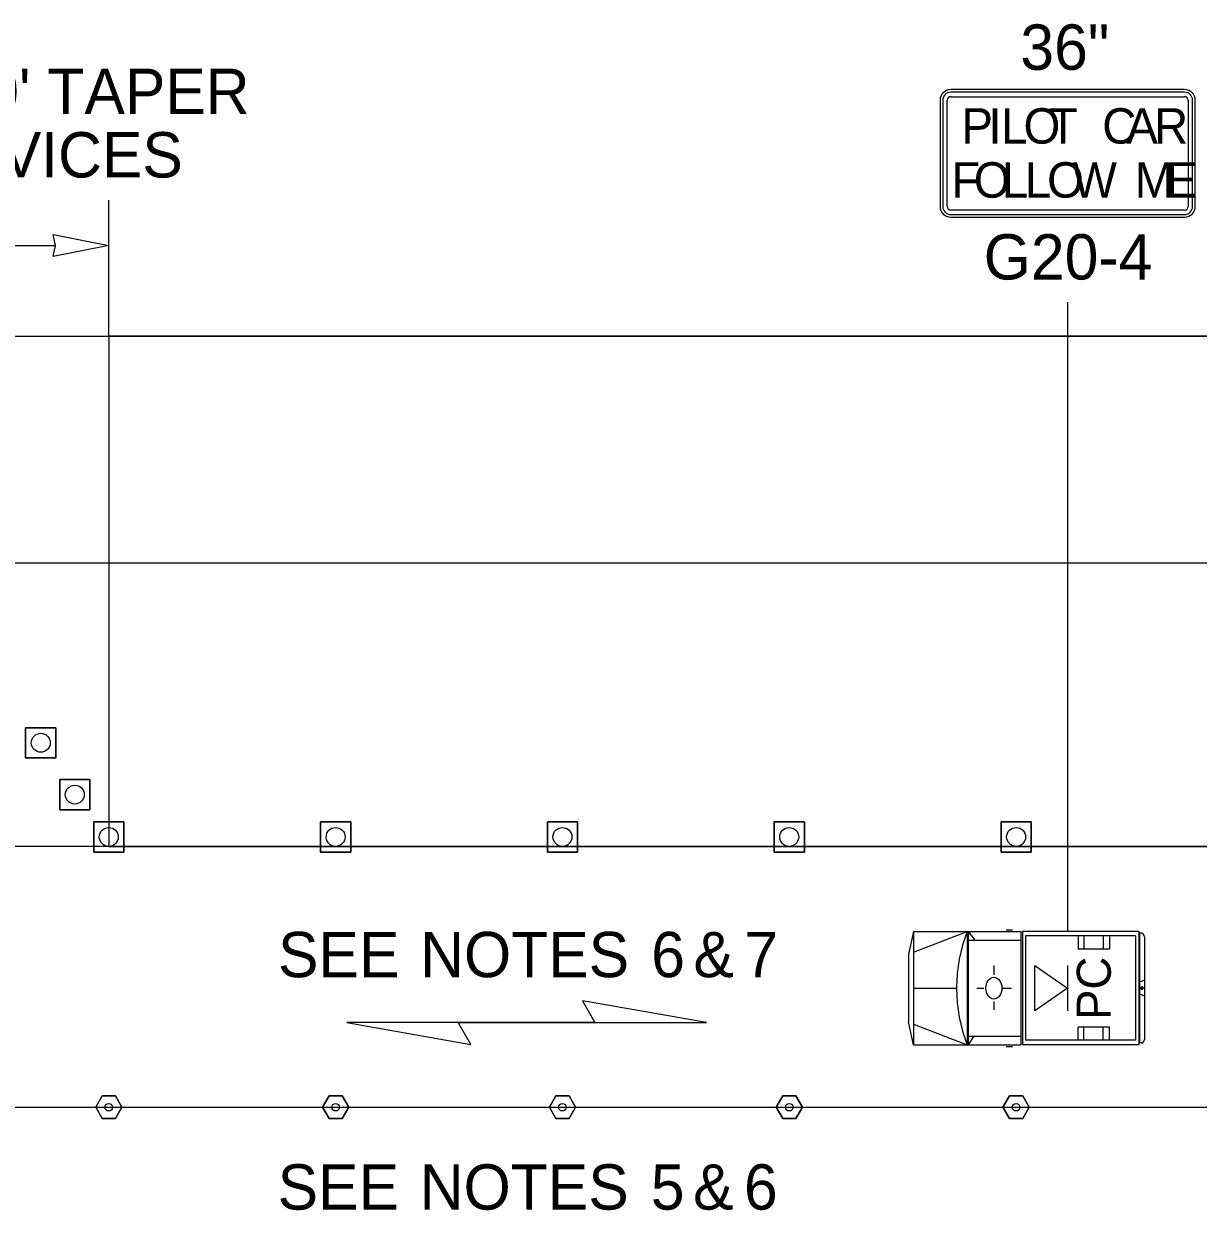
# Model space of a CAD drawing. Extents: x 99999.1 to 100095.7, y 99995 to 100010.7.
# Drawn here: x 100045 to 100047.071, y 100005.95 to 100008.044 of the extents above; entities that cross this region are included whole.
import ezdxf

# ---------------------------------------------------------------- set-up
doc = ezdxf.new("R2010")
doc.units = 0
for name, color, linetype in [('RD_ED_ShoulderPavedEdge', 7, 'Continuous'), ('RD_MK_LineEdgeWhite', 7, 'Continuous'), ('RD_MK_LineSkipCenter', 7, 'Continuous'), ('TR_SN_ConstructionSigns', 7, 'Continuous'), ('TR_WZ_MotoristVehicle', 7, 'Continuous'), ('TR_WZ_PortableSignMountBlk-Wht', 7, 'Continuous'), ('TR_WZ_TrafficCone', 7, 'Continuous'), ('TR_WZ_TubularMarker', 7, 'Continuous'), ('TR_WZ_WorkZoneDetails', 7, 'Continuous'), ('TR_WZ_WorkZoneTextCurrent', 7, 'Continuous')]:
    doc.layers.add(name, color=color, linetype=linetype)

msp = doc.modelspace()

# ---------------------------------------------------------------- linework, layer by layer
at = {"layer": 'RD_ED_ShoulderPavedEdge'}
msp.add_line((100040.1076, 100007.4923), (100055.6424, 100007.4923), dxfattribs=at)
at = {"layer": 'RD_MK_LineEdgeWhite'}
for p, q in [((100040.1076, 100007.0923), (100055.6424, 100007.0923)), ((100040.1076, 100006.1323), (100055.6424, 100006.1323))]:
    msp.add_line(p, q, dxfattribs=at)
at = {"layer": 'RD_MK_LineSkipCenter'}
msp.add_lwpolyline([(100051.15, 100006.5923), (100043.4767, 100006.5923)], dxfattribs=at)
at = {"layer": 'TR_SN_ConstructionSigns'}
for p, q in [((100047.0472, 100007.9273), (100046.6347, 100007.9273)), ((100047.0472, 100007.9226), (100046.6347, 100007.9226)), ((100046.6347, 100007.9148), (100047.0472, 100007.9148)), ((100047.0472, 100007.9226), (100047.0472, 100007.9226)), ((100046.6159, 100007.9086), (100046.6159, 100007.7211)), ((100046.6206, 100007.9086), (100046.6206, 100007.9086)), ((100046.6206, 100007.9086), (100046.6206, 100007.7211)), ((100046.6284, 100007.7211), (100046.6284, 100007.9086)), ((100047.0534, 100007.9086), (100047.0534, 100007.7211)), ((100047.0612, 100007.7211), (100047.0612, 100007.9086)), ((100047.0659, 100007.7211), (100047.0659, 100007.9086)), ((100047.0472, 100007.7148), (100046.6347, 100007.7148)), ((100046.6347, 100007.707), (100046.6347, 100007.707)), ((100046.6347, 100007.707), (100047.0472, 100007.707)), ((100046.6347, 100007.7023), (100047.0472, 100007.7023)), ((100047.0612, 100007.7211), (100047.0612, 100007.7211))]:
    msp.add_line(p, q, dxfattribs=at)
for centre, radius, start, end in [((100046.6347, 100007.9086), 0.0187, 90, 180), ((100046.6347, 100007.9086), 0.0141, 90, 180), ((100046.6347, 100007.9086), 0.00625, 90, 180), ((100047.0472, 100007.9086), 0.0187, 0, 90), ((100047.0472, 100007.9086), 0.0141, 0, 90), ((100047.0472, 100007.9086), 0.00625, 0, 90), ((100046.6347, 100007.7211), 0.0187, 180, 270), ((100046.6347, 100007.7211), 0.0141, 180, 270), ((100046.6347, 100007.7211), 0.00625, 180, 270), ((100047.0472, 100007.7211), 0.0141, 270, 0), ((100047.0472, 100007.7211), 0.00625, 270, 0), ((100047.0472, 100007.7211), 0.0187, 270, 0)]:
    msp.add_arc(centre, radius, start, end, dxfattribs=at)
at = {"layer": 'TR_WZ_MotoristVehicle'}
for p, q in [((100046.5693, 100006.4423), (100046.56, 100006.402)), ((100046.5693, 100006.4423), (100046.5693, 100006.2423)), ((100046.5693, 100006.4423), (100046.7582, 100006.4423)), ((100046.5693, 100006.4057), (100046.6638, 100006.4423)), ((100046.6638, 100006.4423), (100046.6638, 100006.2423)), ((100046.6655, 100006.4423), (100046.6655, 100006.2423)), ((100046.6655, 100006.4423), (100046.6775, 100006.4268)), ((100046.6655, 100006.4268), (100046.7582, 100006.4268)), ((100046.7324, 100006.4451), (100046.7438, 100006.4451)), ((100046.7582, 100006.4423), (100046.7582, 100006.2423)), ((100046.9667, 100006.4423), (100046.761, 100006.4423)), ((100046.761, 100006.4423), (100046.761, 100006.2423)), ((100046.9608, 100006.4344), (100046.7668, 100006.4344)), ((100046.7668, 100006.4344), (100046.7668, 100006.2503)), ((100046.8595, 100006.4344), (100046.8595, 100006.4113)), ((100046.8695, 100006.4344), (100046.8695, 100006.4113)), ((100046.9035, 100006.4344), (100046.9035, 100006.4113)), ((100046.9145, 100006.4344), (100046.9145, 100006.4113)), ((100046.9608, 100006.4344), (100046.9608, 100006.2503)), ((100046.9667, 100006.4423), (100046.9667, 100006.2423)), ((100046.9718, 100006.439), (100046.9674, 100006.439)), ((100046.9674, 100006.439), (100046.9674, 100006.2456)), ((100046.9763, 100006.4329), (100046.9763, 100006.2517)), ((100046.9145, 100006.4113), (100046.8595, 100006.4113)), ((100046.56, 100006.402), (100046.56, 100006.2827)), ((100046.7108, 100006.382), (100046.7108, 100006.3658)), ((100046.5693, 100006.3423), (100046.6452, 100006.3423)), ((100046.6807, 100006.3425), (100046.6933, 100006.3424)), ((100046.7249, 100006.342), (100046.7249, 100006.342)), ((100046.7417, 100006.3416), (100046.7268, 100006.3419)), ((100046.9763, 100006.3564), (100046.9674, 100006.3527)), ((100046.9739, 100006.3423), (100046.9698, 100006.3423)), ((100046.9718, 100006.3451), (100046.9718, 100006.3395)), ((100046.9763, 100006.3282), (100046.9674, 100006.332)), ((100046.7115, 100006.3039), (100046.7112, 100006.3189)), ((100046.5693, 100006.2423), (100046.56, 100006.2827)), ((100046.5693, 100006.279), (100046.6638, 100006.2423)), ((100046.6655, 100006.2578), (100046.7582, 100006.2578)), ((100046.6754, 100006.2578), (100046.6655, 100006.2423)), ((100046.8595, 100006.2503), (100046.8595, 100006.2733)), ((100046.9145, 100006.2733), (100046.8595, 100006.2733)), ((100046.8695, 100006.2503), (100046.8695, 100006.2733)), ((100046.9035, 100006.2503), (100046.9035, 100006.2733)), ((100046.9145, 100006.2503), (100046.9145, 100006.2733)), ((100046.5693, 100006.2423), (100046.7582, 100006.2423)), ((100046.7324, 100006.2395), (100046.7438, 100006.2395)), ((100046.9667, 100006.2423), (100046.761, 100006.2423)), ((100046.9608, 100006.2503), (100046.7668, 100006.2503)), ((100046.9718, 100006.2456), (100046.9674, 100006.2456))]:
    msp.add_line(p, q, dxfattribs=at)
for centre, major_axis, start_param, end_param in [((100046.7987, 100006.3423), (0, -0.2099), 4.215667, 5.208926), ((100046.9718, 100006.4329), (0, 0.0061), 4.712389, 6.283185), ((100046.9718, 100006.2517), (0, -0.0061), 0, 1.570796)]:
    msp.add_ellipse(centre, major_axis=major_axis, ratio=0.73155, start_param=start_param, end_param=end_param, dxfattribs=at)
for centre, major_axis in [((100046.7108, 100006.3423), (0, 0.0193)), ((100046.9718, 100006.3423), (0, 0.00282))]:
    msp.add_ellipse(centre, major_axis=major_axis, ratio=0.73155, dxfattribs=at)
at = {"layer": 'TR_WZ_PortableSignMountBlk-Wht'}
msp.add_line((100046.8406, 100006.3822), (100046.8406, 100006.3022), dxfattribs=at)
msp.add_lwpolyline([(100046.8406, 100006.3423), (100046.7832, 100006.3022), (100046.7832, 100006.3822)], close=True, dxfattribs=at)
at = {"layer": 'TR_WZ_TrafficCone'}
for points in [[(100045.0034, 100006.8017), (100045.0567, 100006.8017), (100045.0567, 100006.7484), (100045.0034, 100006.7484), (100045.0034, 100006.8017)], [(100045.0034, 100006.7484), (100045.0567, 100006.7484), (100045.0567, 100006.8017), (100045.0034, 100006.8017), (100045.0034, 100006.7484)], [(100045.0634, 100006.7104), (100045.1167, 100006.7104), (100045.1167, 100006.6571), (100045.0634, 100006.6571), (100045.0634, 100006.7104)], [(100045.0634, 100006.6571), (100045.1167, 100006.6571), (100045.1167, 100006.7104), (100045.0634, 100006.7104), (100045.0634, 100006.6571)], [(100045.1234, 100006.6357), (100045.1767, 100006.6357), (100045.1767, 100006.5823), (100045.1234, 100006.5823), (100045.1234, 100006.6357)], [(100045.1234, 100006.5823), (100045.1767, 100006.5823), (100045.1767, 100006.6357), (100045.1234, 100006.6357), (100045.1234, 100006.5823)], [(100045.5234, 100006.6357), (100045.5767, 100006.6357), (100045.5767, 100006.5823), (100045.5234, 100006.5823), (100045.5234, 100006.6357)], [(100045.5234, 100006.5823), (100045.5767, 100006.5823), (100045.5767, 100006.6357), (100045.5234, 100006.6357), (100045.5234, 100006.5823)], [(100045.9234, 100006.6357), (100045.9767, 100006.6357), (100045.9767, 100006.5823), (100045.9234, 100006.5823), (100045.9234, 100006.6357)], [(100045.9234, 100006.5823), (100045.9767, 100006.5823), (100045.9767, 100006.6357), (100045.9234, 100006.6357), (100045.9234, 100006.5823)], [(100046.3234, 100006.6357), (100046.3767, 100006.6357), (100046.3767, 100006.5823), (100046.3234, 100006.5823), (100046.3234, 100006.6357)], [(100046.3234, 100006.5823), (100046.3767, 100006.5823), (100046.3767, 100006.6357), (100046.3234, 100006.6357), (100046.3234, 100006.5823)], [(100046.7234, 100006.6357), (100046.7767, 100006.6357), (100046.7767, 100006.5823), (100046.7234, 100006.5823), (100046.7234, 100006.6357)], [(100046.7234, 100006.5823), (100046.7767, 100006.5823), (100046.7767, 100006.6357), (100046.7234, 100006.6357), (100046.7234, 100006.5823)]]:
    msp.add_lwpolyline(points, dxfattribs=at)
for centre in [(100045.03, 100006.7751), (100045.09, 100006.6837), (100045.15, 100006.609), (100045.55, 100006.609), (100045.95, 100006.609), (100046.35, 100006.609), (100046.75, 100006.609)]:
    msp.add_circle(centre, 0.0167, dxfattribs=at)
at = {"layer": 'TR_WZ_TubularMarker'}
for points in [[(100045.1269, 100006.1323), (100045.1385, 100006.1523), (100045.1616, 100006.1523), (100045.1731, 100006.1323), (100045.1616, 100006.1123), (100045.1385, 100006.1123)], [(100045.5269, 100006.1323), (100045.5385, 100006.1523), (100045.5616, 100006.1523), (100045.5731, 100006.1323), (100045.5616, 100006.1123), (100045.5385, 100006.1123)], [(100045.9269, 100006.1323), (100045.9385, 100006.1523), (100045.9616, 100006.1523), (100045.9731, 100006.1323), (100045.9616, 100006.1123), (100045.9385, 100006.1123)], [(100046.3269, 100006.1323), (100046.3385, 100006.1523), (100046.3616, 100006.1523), (100046.3731, 100006.1323), (100046.3616, 100006.1123), (100046.3385, 100006.1123)], [(100046.7269, 100006.1323), (100046.7385, 100006.1523), (100046.7616, 100006.1523), (100046.7731, 100006.1323), (100046.7616, 100006.1123), (100046.7385, 100006.1123)]]:
    msp.add_lwpolyline(points, close=True, dxfattribs=at)
for points in [[(100045.1385, 100006.1123), (100045.1616, 100006.1123), (100045.1731, 100006.1323), (100045.1616, 100006.1523), (100045.1385, 100006.1523), (100045.1269, 100006.1323), (100045.1385, 100006.1123)], [(100045.5385, 100006.1123), (100045.5616, 100006.1123), (100045.5731, 100006.1323), (100045.5616, 100006.1523), (100045.5385, 100006.1523), (100045.5269, 100006.1323), (100045.5385, 100006.1123)], [(100045.9385, 100006.1123), (100045.9616, 100006.1123), (100045.9731, 100006.1323), (100045.9616, 100006.1523), (100045.9385, 100006.1523), (100045.9269, 100006.1323), (100045.9385, 100006.1123)], [(100046.3385, 100006.1123), (100046.3616, 100006.1123), (100046.3731, 100006.1323), (100046.3616, 100006.1523), (100046.3385, 100006.1523), (100046.3269, 100006.1323), (100046.3385, 100006.1123)], [(100046.7385, 100006.1123), (100046.7616, 100006.1123), (100046.7731, 100006.1323), (100046.7616, 100006.1523), (100046.7385, 100006.1523), (100046.7269, 100006.1323), (100046.7385, 100006.1123)]]:
    msp.add_lwpolyline(points, dxfattribs=at)
for centre in [(100045.15, 100006.1323), (100045.55, 100006.1323), (100045.95, 100006.1323), (100046.35, 100006.1323), (100046.75, 100006.1323)]:
    msp.add_circle(centre, 0.00667, dxfattribs=at)
at = {"layer": 'TR_WZ_WorkZoneDetails'}
for p, q in [((100045.15, 100007.4923), (100045.15, 100007.7323)), ((100044.9204, 100007.6523), (100045.0563, 100007.6523)), ((100046.8406, 100007.5523), (100046.8406, 100006.4423)), ((100045.7663, 100006.2816), (100046.0074, 100006.2816)), ((100046.0074, 100006.2816), (100045.7663, 100006.2816))]:
    msp.add_line(p, q, dxfattribs=at)
for points in [[(100045.15, 100007.6523), (100045.0517, 100007.6331), (100045.0563, 100007.6523), (100045.0517, 100007.6716)], [(100045.15, 100007.4923), (100045.15, 100006.5923), (100049.9338, 100006.5923), (100049.9338, 100007.4923)], [(100046.2039, 100006.2816), (100045.9851, 100006.3202), (100046.0074, 100006.2816)], [(100045.5698, 100006.2816), (100045.7886, 100006.243), (100045.7663, 100006.2816)]]:
    msp.add_lwpolyline(points, close=True, dxfattribs=at)

# ---------------------------------------------------------------- texts
at = {"layer": 'TR_SN_ConstructionSigns'}
for s, p in [('36"', (100046.7575, 100007.9623)), ('G20-4', (100046.6929, 100007.5923))]:
    msp.add_text(s, height=0.08, rotation=360, dxfattribs=at).set_placement(p)
for s, p in [('P', (100046.6537, 100007.832)), ('I', (100046.7012, 100007.832)), ('L', (100046.7237, 100007.832)), ('O', (100046.7631, 100007.832)), ('T', (100046.8075, 100007.832)), ('C', (100046.9018, 100007.832)), ('A', (100046.9443, 100007.832)), ('R', (100046.9931, 100007.832)), ('F', (100046.6359, 100007.7367)), ('O', (100046.6753, 100007.7367)), ('L', (100046.7247, 100007.7367)), ('L', (100046.7653, 100007.7367)), ('O', (100046.8047, 100007.7367)), ('W', (100046.849, 100007.7367)), ('M', (100046.959, 100007.7367)), ('E', (100047.014, 100007.7367))]:
    msp.add_text(s, height=0.0625, dxfattribs=at).set_placement(p)
at = {"layer": 'TR_WZ_MotoristVehicle'}
msp.add_text('PC', height=0.06, rotation=90, dxfattribs=at).set_placement((100046.917, 100006.2863))
at = {"layer": 'TR_WZ_WorkZoneTextCurrent'}
for s, p in [("50' - 100' TAPER", (100044.5786, 100007.8843)), ('6+ DEVICES', (100044.6592, 100007.7723))]:
    msp.add_text(s, height=0.08, rotation=360, dxfattribs=at).set_placement(p)
for s, p in [('SEE', (100045.4485, 100006.3616)), ('NOTES', (100045.6991, 100006.3616)), ('6', (100046.1066, 100006.3616)), ('&', (100046.181, 100006.3616)), ('7', (100046.2708, 100006.3616)), ('SEE', (100045.4478, 100005.9516)), ('NOTES', (100045.6984, 100005.9516)), ('5', (100046.1059, 100005.9516)), ('&', (100046.1803, 100005.9516)), ('6', (100046.2701, 100005.9516))]:
    msp.add_text(s, height=0.08, dxfattribs=at).set_placement(p)

doc.saveas('drawing.dxf')
